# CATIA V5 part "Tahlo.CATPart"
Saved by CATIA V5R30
Part number: Tahlo
Bounding box of the stored display mesh (mm): x -18 to 200, y -12.495 to 12.495, z -12.495 to 12.495
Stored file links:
  E:\Bakalarka\Model\Forma_v7\Tahlo.CATPart
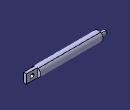
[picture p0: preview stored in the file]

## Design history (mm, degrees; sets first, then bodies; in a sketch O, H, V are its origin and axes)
Body1 (main body)
  Sketch1 on zx-plane, origin (0, 0, 0), H (-1, 0, 0), V (0, 0, 1)
    line L1 (0, 0) -> (-200, 0)
    line L2 (-200, 0) -> (-200, 12.5)
    line L3 (-200, 12.5) -> (0, 12.5)
    line L4 (0, 12.5) -> (0, 5)
    point P3 (0, 12.5)
    line L5 (0, 5) -> (18, 5)
    line L6 (18, 5) -> (18, 0)
    line L7 (18, 0) -> (0, 0)
    point P6 (18, 0)
    point P7 (0, 0)
    length L1 = 200
    length L5 = 18
    distance P6 O = 18
    distance P3 O = 12.5
    length L6 = 5
    length L4 = 7.5
    distance P7 O = 0
    horizontal: L1 H, L3 H, L5 H, L7 H
    vertical: L2 V, L4 V
    coincidence: P6 H
  Shaft1: profile Sketch1, axis Sketch1.L1, angle 360
  Thread1: diameter 10, depth 18, pitch 1, on face of Shaft1 from Sketch1.L5, from face of Shaft1 from Sketch1.L6
  Sketch2 on face of Shaft1 from Sketch1.L2, origin (200, 0, 0), H (0, 1, 0), V (0, 0, 1)
    projected circle E1 centre (0, 0) radius 12.5 from edge [face of Shaft1 from Sketch1.L2 | face of Shaft1 from Sketch1.L3]
    projected arc E2 centre (0, 0) radius 12.5 from (-4, 11.8427) to (-4, -11.8427) ccw from edge [face of Shaft1 from Sketch1.L2 | face of Shaft1 from Sketch1.L3]
    projected arc E3 centre (0, 0) radius 12.5 from (4, -11.8427) to (4, 11.8427) ccw from edge [face of Shaft1 from Sketch1.L2 | face of Shaft1 from Sketch1.L3]
    line L1 (4, 11.8427) -> (4, -11.8427)
    point P1 (4, 11.8427)
    point P2 (4, -11.8427)
    line L2 (-4, 11.8427) -> (-4, -11.8427)
    point P3 (-4, 11.8427)
    point P4 (-4, -11.8427)
    distance L2 L1 = 8
    distance L1 V = 4
    coincidence: P1 E1, P2 E1, P3 E1, P4 E1
    vertical: L1 V, L2 V
  Pocket1: profile Sketch2, direction (-1, 0, 0), length 30
  Sketch3 on face of Pocket1 from Sketch2.L1, origin (0, 4, 0), H (-1, 0, 0), V (0, 0, 1)
    circle A1 centre (-185, 0) radius 5
    point P1 (-185, 0)
    radius A1 = 5
    distance A1 V = 180
    coincidence: P1 H
  Pocket2: profile Sketch3, direction (0, -1, 0), through (limit type 6)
